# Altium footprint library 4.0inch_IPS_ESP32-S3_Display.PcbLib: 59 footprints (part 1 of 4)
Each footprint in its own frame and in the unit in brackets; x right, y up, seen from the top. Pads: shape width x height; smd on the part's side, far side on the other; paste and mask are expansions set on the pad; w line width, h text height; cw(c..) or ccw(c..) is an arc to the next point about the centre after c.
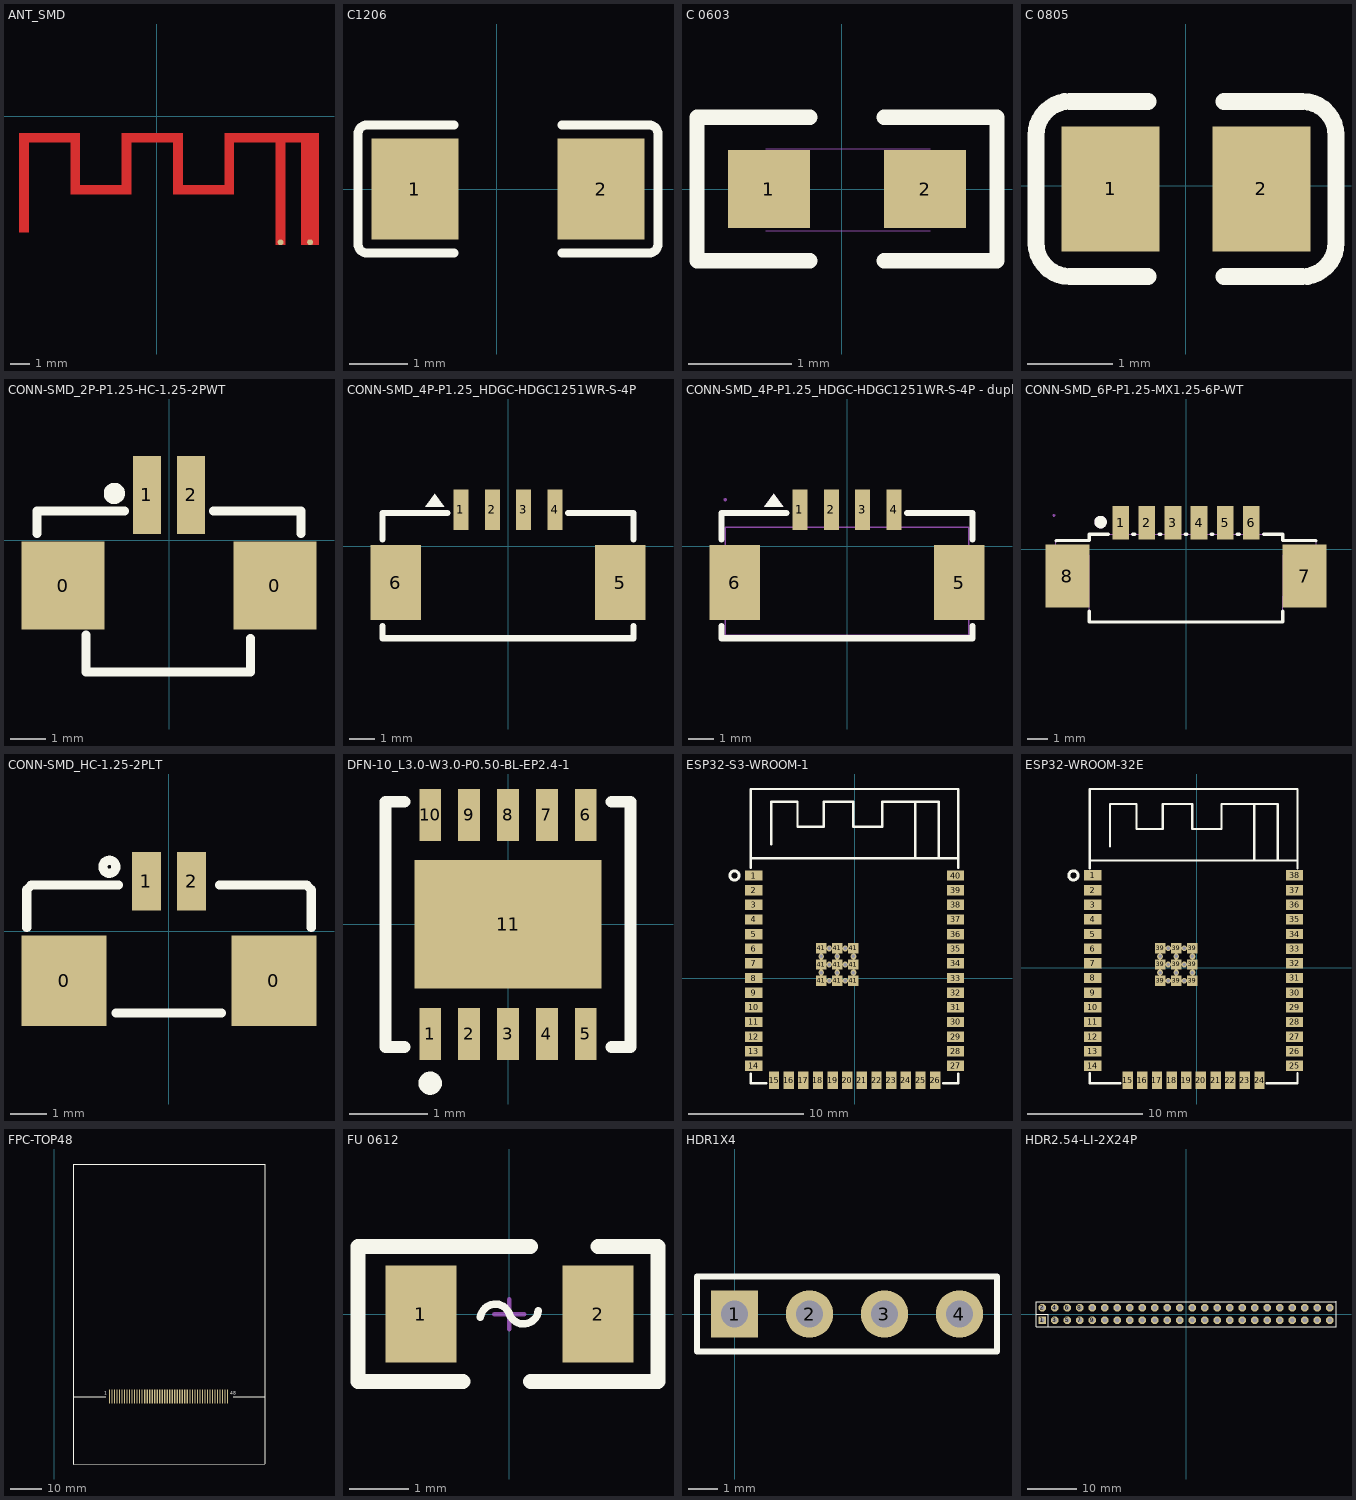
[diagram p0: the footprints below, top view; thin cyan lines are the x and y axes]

## ANT_SMD [mm]
pads (2):
  round 0.3 smd mask+0.102: 1(6.272,-6.391) 2(7.772,-6.391)
Top Layer:
  region: 8.222,-0.841 7.322,-0.841 7.322,-6.541 8.222,-6.541
  region: 6.522,-0.841 6.022,-0.841 6.022,-6.541 6.522,-6.541
  region: 8.222,-0.841 3.672,-0.841 3.672,-1.341 8.222,-1.341
  region: -6.478,-0.841 -6.978,-0.841 -6.978,-5.906 -6.478,-5.906
  region: -3.878,-0.841 -4.378,-0.841 -4.378,-3.981 -3.878,-3.981
  region: -1.278,-0.841 -1.778,-0.841 -1.778,-3.981 -1.278,-3.981
  region: 1.322,-0.841 0.822,-0.841 0.822,-3.981 1.322,-3.981
  region: 3.922,-0.841 3.422,-0.841 3.422,-3.981 3.922,-3.981
  region: 3.922,-3.481 0.856,-3.481 0.856,-3.981 3.922,-3.981
  region: -1.278,-3.481 -4.378,-3.481 -4.378,-3.981 -1.278,-3.981
  region: 1.322,-0.841 -1.778,-0.841 -1.778,-1.341 1.322,-1.341
  region: -3.878,-0.841 -6.978,-0.841 -6.978,-1.341 -3.878,-1.341

## C1206 [mm]
pads (2):
  rect 1.485x1.728 smd paste-100 mask+0.051: 1(-1.397,0) 2(1.788,0)
Top Overlay:
  lines w0.152: -0.731,-1.093 -2.216,-1.093 cw(c-2.216,-0.94) -2.368,-0.94 -2.368,0.94 cw(c-2.216,0.94) -2.216,1.093 -0.731,1.093 ; 1.122,-1.093 2.607,-1.093 ccw(c2.607,-0.94) 2.759,-0.94 2.759,0.94 ccw(c2.607,0.94) 2.607,1.093 1.122,1.093
Top Paste:
  region: 1.046,-0.764 1.046,-0.394 1.146,-0.294 1.45,-0.294 1.55,-0.194 1.55,0.194 1.45,0.294 1.146,0.294 1.046,0.394 1.046,0.764 1.146,0.864 2.431,0.864 2.531,0.764 2.531,-0.764 2.431,-0.864 1.146,-0.864
  region: -0.654,-0.764 -0.654,-0.394 -0.754,-0.294 -1.059,-0.294 -1.159,-0.194 -1.159,0.194 -1.059,0.294 -0.754,0.294 -0.654,0.394 -0.654,0.764 -0.754,0.864 -2.039,0.864 -2.139,0.764 -2.139,-0.764 -2.039,-0.864 -0.754,-0.864

## C 0603 [mm] "无极性贴片电容"
pads (2):
  rect 0.8x0.76 smd: 1(-0.711,0) 2(0.809,0)
Top Overlay:
  lines w0.15: -0.311,-0.7 -1.411,-0.7 -1.411,0.7 -0.311,0.7 ; 0.409,-0.7 1.509,-0.7 1.509,0.7 0.409,0.7
Mechanical 13:
  lines w0.01: -0.742,-0.406 0.858,-0.406 ; -0.742,0.394 0.858,0.394
3D body "C 0603.STEP": height 0.81, standoff -0.01, extent -0.742,-0.41 0.858,0.41

## C 0805 [mm] "无极性贴片电容"
height 0.5
pads (2):
  rect 1.16x1.47 smd: 1(-0.885,-0.039) 2(0.895,-0.039)
Top Overlay:
  lines w0.2: -0.445,-1.074 -1.365,-1.074 cw(c-1.365,-0.674) -1.765,-0.674 -1.765,0.596 cw(c-1.365,0.596) -1.365,0.996 -0.445,0.996 ; 0.455,-1.074 1.375,-1.074 ccw(c1.375,-0.674) 1.775,-0.674 1.775,0.596 ccw(c1.375,0.596) 1.375,0.996 0.455,0.996
3D body "User Library-0805 SMD Capacitor.STEP": height 0.77, standoff -0.01, extent -0.995,-0.664 1.005,0.586

## CONN-SMD_2P-P1.25-HC-1.25-2PWT [mm]
pads (4):
  rect 2.35x2.5 smd paste+0 mask+0.05: 0(-3.005,-1.285) 0(3.005,-1.285)
  rect 0.8x2.2 smd paste+0 mask+0.05: 1(-0.625,1.285) 2(0.625,1.285)
Top Overlay:
  circle w0.3: c-1.55,1.33 r0.15
  lines w0.254: -3.75,0.196 -3.75,0.835 -1.256,0.835 ; -2.36,-2.69 -2.36,-3.73 2.31,-3.73 2.31,-2.78 ; 1.256,0.835 3.75,0.835 3.75,0.196
3D body "User Library-ZH1_5-2P.STEP": height 5, standoff 0, extent -2.966,-2.968 3.034,2.232

## CONN-SMD_4P-P1.25_HDGC-HDGC1251WR-S-4P [mm]
pads (6):
  rect 0.6x1.6 smd mask+0.05: 1(-1.875,1.45) 2(-0.625,1.45) 3(0.625,1.45) 4(1.875,1.45)
  rect 2x3 smd mask+0.05: 5(4.475,-1.45) 6(-4.475,-1.45)
Top Overlay:
  region: -3.175,1.577 -3.302,1.577 -2.921,2.085 -2.54,1.577 -3.175,1.577
  lines w0.254: -5,-3.181 -5,-3.669 5,-3.669 5,-3.181 ; -5,0.281 -5,1.323 -2.413,1.323 ; 2.406,1.323 5,1.323 5,0.281
3D body "xb-x125-pcb-123.stp": height 3.5, standoff -0.1, extent -5.227,-3.975 5.163,1.525

## CONN-SMD_4P-P1.25_HDGC-HDGC1251WR-S-4P - duplicate [mm]
pads (6):
  rect 0.6x1.6 smd mask+0.05: 1(-1.875,1.45) 2(-0.625,1.45) 3(0.625,1.45) 4(1.875,1.45)
  rect 2x3 smd mask+0.05: 5(4.475,-1.45) 6(-4.475,-1.45)
Top Overlay:
  region: -3.175,1.577 -3.302,1.577 -2.921,2.085 -2.54,1.577 -3.175,1.577
  lines w0.254: -5,-3.181 -5,-3.669 5,-3.669 5,-3.181 ; -5,0.281 -5,1.323 -2.413,1.323 ; 2.406,1.323 5,1.323 5,0.281
Mechanical 6:
  region: -3.175,1.577 -3.302,1.577 -2.921,2.085 -2.54,1.577 -3.175,1.577
Mechanical 15:
  region: -4.85,-0.323 -3.65,-0.323 -3.65,-2.323 -4.85,-2.323
  region: 3.65,-0.323 4.85,-0.323 4.85,-2.323 3.65,-2.323
  region: -2.025,1.858 -1.725,1.858 -1.725,0.658 -2.025,0.658
  region: -0.775,1.858 -0.475,1.858 -0.475,0.658 -0.775,0.658
  region: 0.475,1.858 0.775,1.858 0.775,0.658 0.475,0.658
  region: 1.725,1.858 2.025,1.858 2.025,0.658 1.725,0.658
  region: -4.79,1.858 -4.79,1.883 -4.825,1.918 -4.875,1.918 -4.91,1.883 -4.91,1.858 -4.91,1.833 -4.875,1.798 -4.825,1.798 -4.79,1.833
  lines w0.051: -4.85,-3.542 4.85,-3.542 4.85,0.758 -4.85,0.758 -4.85,-3.542

## CONN-SMD_6P-P1.25-MX1.25-6P-WT [mm]
pads (8):
  rect 0.8x1.6 smd paste+0 mask+0.05: 1(-3.125,1.275) 2(-1.875,1.275) 3(-0.625,1.275) 4(0.625,1.275) 5(1.875,1.275) 6(3.125,1.275)
  rect 2.1x3 smd paste+0 mask+0.05: 7(5.675,-1.275) 8(-5.675,-1.275)
Top Overlay:
  circle w0.3: c-4.085,1.305 r0.15
  lines w0.152: -6.225,0.405 -6.225,0.425 -4.625,0.425 -4.625,0.725 -3.705,0.725 ; -4.625,-2.955 -4.625,-3.475 3.375,-3.475 4.625,-3.475 4.625,-2.955 ; -2.545,0.725 -2.455,0.725 ; -1.295,0.725 -1.205,0.725 ; -0.045,0.725 0.045,0.725 ; 2.455,0.725 2.545,0.725 ; 3.705,0.725 4.625,0.725 4.625,0.425 6.225,0.425 6.225,0.405 ; 1.205,0.725 1.295,0.725 1.205,0.725
Mechanical 6:
  circle w0.3: c-4.085,1.305 r0.15
Mechanical 15:
  region: -6.265,1.625 -6.266,1.649 -6.301,1.683 -6.349,1.683 -6.384,1.649 -6.385,1.625 -6.384,1.601 -6.349,1.567 -6.301,1.567 -6.266,1.601
  region: -6.125,-2.275 -6.325,-2.075 -6.325,-0.465 -6.125,-0.265 -4.625,-0.265 -4.625,-2.275
  region: 6.125,-0.265 6.325,-0.465 6.325,-2.075 6.125,-2.275 4.625,-2.275 4.625,-0.265
  region: 1.725,1.625 2.025,1.625 2.025,0.625 1.725,0.625
  region: 0.475,1.625 0.775,1.625 0.775,0.625 0.475,0.625
  region: -0.775,1.625 -0.475,1.625 -0.475,0.625 -0.775,0.625
  region: -2.025,1.625 -1.725,1.625 -1.725,0.625 -2.025,0.625
  region: -3.275,1.625 -2.975,1.625 -2.975,0.625 -3.275,0.625
  region: 2.975,1.625 3.275,1.625 3.275,0.625 2.975,0.625
  lines w0.051: -6.225,-2.275 -4.625,-2.275 -4.625,-3.475 4.625,-3.475 4.625,-2.275 6.225,-2.275 6.225,0.425 4.625,0.425 4.625,0.725 -4.625,0.725 -4.625,0.715 -4.625,0.425 -6.225,0.425 -6.225,-2.275

## CONN-SMD_HC-1.25-2PLT [mm]
pads (4):
  rect 2.35x2.5 smd paste+0 mask+0.05: 0(-2.9,-1.38) 0(2.9,-1.38)
  rect 0.8x1.62 smd paste+0 mask+0.05: 1(-0.625,1.38) 2(0.625,1.38)
Top Overlay:
  circle w0.254: c-1.651,1.778 r0.18
  lines w0.254: -3.937,0.101 -3.937,1.143 -3.81,1.27 -1.397,1.27 ; -1.47,-2.27 1.451,-2.27 ; 1.397,1.27 3.81,1.27 3.937,1.143 3.937,0.101
3D body "2pin.STEP": height 3.4, standoff 0, extent -3.759,-3.358 3.741,1.892

## DFN-10_L3.0-W3.0-P0.50-BL-EP2.4-1 [mm]
pads (11):
  rect 0.28x0.665 smd: 1(-1,-1.407) 2(-0.5,-1.407) 3(0,-1.407) 4(0.5,-1.407) 5(1,-1.407) 6(1,1.407) 7(0.5,1.407) 8(0,1.407) 9(-0.5,1.407) 10(-1,1.407)
  rect 2.4x1.65 smd: 11(0,0)
Top Overlay:
  circle w0.15: c-1,-2.04 r0.075
  lines w0.152: -1.331,-1.576 -1.576,-1.576 -1.576,1.576 -1.331,1.576 ; 1.331,-1.576 1.576,-1.576 1.576,1.576 1.331,1.576

## ESP32-S3-WROOM-1 [mm] "ESP32-S3-WROOM-1"
pads (49):
  rect 1.5x0.9 smd mask+0.05: 1(-8.75,8.895) 2(-8.75,7.625) 3(-8.75,6.355) 4(-8.75,5.085) 5(-8.75,3.815) 6(-8.75,2.545) 7(-8.75,1.275) 8(-8.75,0.005) 9(-8.75,-1.265) 10(-8.75,-2.535) 11(-8.75,-3.805) 12(-8.75,-5.075) 13(-8.75,-6.345) 14(-8.75,-7.615) 27(8.75,-7.615) 28(8.75,-6.345) 29(8.75,-5.075) 30(8.75,-3.805) 31(8.75,-2.535) 32(8.75,-1.265) 33(8.75,0.005) 34(8.75,1.275) 35(8.75,2.545) 36(8.75,3.815) 37(8.75,5.085) 38(8.75,6.355) 39(8.75,7.625) 40(8.75,8.895)
  rect 0.9x1.5 smd mask+0.05: 15(-6.985,-8.865) 16(-5.715,-8.865) 17(-4.445,-8.865) 18(-3.175,-8.865) 19(-1.905,-8.865) 20(-0.635,-8.865) 21(0.635,-8.865) 22(1.905,-8.865) 23(3.175,-8.865) 24(4.445,-8.865) 25(5.715,-8.865) 26(6.985,-8.865)
  rect 0.9x0.9 smd mask+0.051: 41(-2.9,-0.225) 41(-2.9,1.175) 41(-2.9,2.575) 41(-1.5,-0.225) 41(-1.5,1.175) 41(-1.5,2.575) 41(-0.1,-0.225) 41(-0.1,1.175) 41(-0.1,2.575)
via -0.8,-0.225 diameter 0.5 hole 0.3
via -2.2,-0.225 diameter 0.5 hole 0.3
via -2.2,1.175 diameter 0.5 hole 0.3
via -0.8,1.175 diameter 0.5 hole 0.3
via -0.8,2.575 diameter 0.5 hole 0.3
via -0.1,1.875 diameter 0.5 hole 0.3
via -0.1,0.475 diameter 0.5 hole 0.3
via -2.9,0.475 diameter 0.5 hole 0.3
via -2.9,1.875 diameter 0.5 hole 0.3
via -2.2,2.575 diameter 0.5 hole 0.3
via -1.5,0.475 diameter 0.5 hole 0.3
via -1.5,1.875 diameter 0.5 hole 0.3
Top Overlay:
  circle w0.254: c-10.414,8.895 r0.402
  lines w0.203: -9,-8.296 -9,-9.115 -7.666,-9.115 ; -9,9.576 -9,16.395 9,16.395 9,9.576 ; -9,10.395 9,10.395 ; -7.239,11.597 -7.239,15.28 -4.953,15.28 -4.953,13.121 -2.667,13.121 -2.667,15.28 -0.127,15.28 -0.127,13.121 2.413,13.121 2.413,15.28 5.265,15.28 5.265,10.395 ; 5.062,15.28 7.297,15.28 7.297,10.395 ; 7.666,-9.115 9,-9.115 9,-8.296
3D body "ESP32-S3-WROOM-1_20211021.STEP": height 3.1, standoff 0, extent -9,-9.115 9,16.385

## ESP32-WROOM-32E [mm]
pads (47):
  rect 1.5x0.9 smd mask+0.051: 1(-9.004,7.987) 2(-9.004,6.717) 3(-9.004,5.447) 4(-9.004,4.177) 5(-9.004,2.907) 6(-9.004,1.637) 7(-9.004,0.367) 8(-9.004,-0.903) 9(-9.004,-2.173) 10(-9.004,-3.443) 11(-9.004,-4.713) 12(-9.004,-5.983) 13(-9.004,-7.253) 14(-9.004,-8.523) 25(8.496,-8.523) 26(8.496,-7.253) 27(8.496,-5.983) 28(8.496,-4.713) 29(8.496,-3.443) 30(8.496,-2.173) 31(8.496,-0.903) 32(8.496,0.367) 33(8.496,1.637) 34(8.496,2.907) 35(8.496,4.177) 36(8.496,5.447) 37(8.496,6.717) 38(8.496,7.987)
  rect 0.9x1.5 smd mask+0.051: 15(-5.969,-9.774) 16(-4.699,-9.774) 17(-3.429,-9.774) 18(-2.159,-9.774) 19(-0.889,-9.774) 20(0.381,-9.774) 21(1.651,-9.774) 22(2.921,-9.774) 23(4.191,-9.774) 24(5.461,-9.774)
  rect 0.9x0.9 smd mask+0.051: 39(-3.154,-1.133) 39(-3.154,0.267) 39(-3.154,1.667) 39(-1.754,0.267) 39(-1.754,-1.133) 39(-1.754,1.667) 39(-0.354,-1.133) 39(-0.354,0.267) 39(-0.354,1.667)
via -1.754,0.967 diameter 0.5 hole 0.3
via -1.754,-0.433 diameter 0.5 hole 0.3
via -2.454,1.667 diameter 0.5 hole 0.3
via -3.154,0.967 diameter 0.5 hole 0.3
via -3.154,-0.433 diameter 0.5 hole 0.3
via -0.354,-0.433 diameter 0.5 hole 0.3
via -0.354,0.967 diameter 0.5 hole 0.3
via -1.054,1.667 diameter 0.5 hole 0.3
via -1.054,0.267 diameter 0.5 hole 0.3
via -2.454,0.267 diameter 0.5 hole 0.3
via -2.454,-1.133 diameter 0.5 hole 0.3
via -1.054,-1.133 diameter 0.5 hole 0.3
Top Overlay:
  circle w0.254: c-10.668,7.986 r0.402
  lines w0.203: -9.254,-9.15 -9.254,-10.023 -6.596,-10.023 ; -9.254,8.613 -9.254,15.476 8.746,15.477 8.746,8.614 ; -9.254,9.287 8.746,9.287 ; -7.493,10.489 -7.493,14.172 -5.207,14.172 -5.207,12.013 -2.921,12.013 -2.921,14.172 -0.381,14.172 -0.381,12.013 2.159,12.013 2.159,14.172 5.011,14.172 5.011,9.287 ; 4.808,14.172 7.043,14.172 7.043,9.287 ; 6.088,-10.023 8.746,-10.023 8.746,-9.15
3D body "ESP32-WROOM-32E_20210903.STEP": height 3.2, standoff 0.1, extent -9.254,-10.023 8.746,15.477

## FPC-TOP48 [mm]
pads (48):
  rect 0.4x4.5 smd: 1(17.542,-85.171) 2(18.342,-85.171) 3(19.142,-85.171) 4(19.942,-85.171) 5(20.742,-85.171) 6(21.542,-85.171) 7(22.342,-85.171) 8(23.142,-85.171) 9(23.942,-85.171) 10(24.742,-85.171) 11(25.542,-85.171) 12(26.342,-85.171) 13(27.142,-85.171) 14(27.942,-85.171) 15(28.742,-85.171) 16(29.542,-85.171) 17(30.342,-85.171) 18(31.142,-85.171) 19(31.942,-85.171) 20(32.742,-85.171) 21(33.542,-85.171) 22(34.342,-85.171) 23(35.142,-85.171) 24(35.942,-85.171) 25(36.742,-85.171) 26(37.542,-85.171) 27(38.342,-85.171) 28(39.142,-85.171) 29(39.942,-85.171) 30(40.742,-85.171) 31(41.542,-85.171) 32(42.342,-85.171) 33(43.142,-85.171) 34(43.942,-85.171) 35(44.742,-85.171) 36(45.542,-85.171) 37(46.342,-85.171) 38(47.142,-85.171) 39(47.942,-85.171) 40(48.742,-85.171) 41(49.542,-85.171) 42(50.342,-85.171) 43(51.142,-85.171) 44(51.942,-85.171) 45(52.742,-85.171) 46(53.542,-85.171) 47(54.342,-85.171) 48(55.142,-85.171)
Top Overlay:
  lines w0.2: 5.972,-85.171 16.312,-85.171 ; 56.882,-85.171 67.022,-85.171
  lines w0.254: 67.022,-11.171 5.972,-11.171 5.972,-106.601 67.022,-106.601 67.022,-11.144
  text "48" at 56.027,-84.492 h1.02
  text "1" at 15.968,-84.492 h1.02

## FU 0612 [mm] "贴片保险丝"
pads (2):
  rect 1.2x1.65 smd: 1(-1.5,0) 2(1.5,0)
Top Overlay:
  lines w0.127: -0.491,-0.058 cw(c-0.239,-0.087) 0,0 ccw(c0.239,0.087) 0.491,0.058
  lines w0.254: -0.786,-1.143 -2.564,-1.143 -2.564,1.143 -0.786,1.143 0.357,1.143 ; 0.357,-1.143 1.881,-1.143 ; 1.5,1.143 2.516,1.143 2.516,-1.143 1.627,-1.143
Mechanical 15:
  lines w0.076: -0.254,0 0.254,0 ; 0,-0.254 0,0.254
3D body "FU 0805.STEP": height 0.52, standoff 0, extent -1,-0.61 1,0.61

## HDR1X4 [mm] "Connector; Header; 4 Position"
pads (4):
  rect 1.6x1.6 hole 0.9: 1(0,0)
  round 1.6 hole 0.9: 2(2.54,0) 3(5.08,0) 4(7.62,0)
Top Overlay:
  lines w0.203: -1.27,-1.27 -1.27,1.27 8.89,1.27 8.89,-1.27 -1.27,-1.27

## HDR2.54-LI-2X24P [mm] "双排排针，24x2脚"
pads (48):
  rect 1.6x1.6 hole 0.9: 1(-29.21,-1.27)
  round 1.6 hole 0.9: 2(-29.21,1.27) 3(-26.67,-1.27) 4(-26.67,1.27) 5(-24.13,-1.27) 6(-24.13,1.27) 7(-21.59,-1.27) 8(-21.59,1.27) 9(-19.05,-1.27) 10(-19.05,1.27) 11(-16.51,-1.27) 12(-16.51,1.27) 13(-13.97,-1.27) 14(-13.97,1.27) 15(-11.43,-1.27) 16(-11.43,1.27) 17(-8.89,-1.27) 18(-8.89,1.27) 19(-6.35,-1.27) 20(-6.35,1.27) 21(-3.81,-1.27) 22(-3.81,1.27) 23(-1.27,-1.27) 24(-1.27,1.27) 25(1.27,-1.27) 26(1.27,1.27) 27(3.81,-1.27) 28(3.81,1.27) 29(6.35,-1.27) 30(6.35,1.27) 31(8.89,-1.27) 32(8.89,1.27) 33(11.43,-1.27) 34(11.43,1.27) 35(13.97,-1.27) 36(13.97,1.27) 37(16.51,-1.27) 38(16.51,1.27) 39(19.05,-1.27) 40(19.05,1.27) 41(21.59,-1.27) 42(21.59,1.27) 43(24.13,-1.27) 44(24.13,1.27) 45(26.67,-1.27) 46(26.67,1.27) 47(29.21,-1.27) 48(29.21,1.27)
Top Overlay:
  lines w0.2: -30.48,0 -27.94,0 -27.94,-2.54 ; 30.48,-2.54 -30.48,-2.54 -30.48,2.54 30.48,2.54
  lines w0.203: 30.48,-2.54 30.48,2.54
3D body "HDR2.54-1x2P.STEP": height 8.5, standoff -3, extent 20.32,-2.54 22.86,2.54
3D body "HDR2.54-1x2P.STEP": height 8.5, standoff -3, extent 25.4,-2.54 27.94,2.54
3D body "HDR2.54-1x2P.STEP": height 8.5, standoff -3, extent 22.86,-2.54 25.4,2.54
3D body "HDR2.54-1x2P.STEP": height 8.5, standoff -3, extent 12.7,-2.54 15.24,2.54
3D body "HDR2.54-1x2P.STEP": height 8.5, standoff -3, extent 15.24,-2.54 17.78,2.54
3D body "HDR2.54-1x2P.STEP": height 8.5, standoff -3, extent 7.62,-2.54 10.16,2.54
3D body "HDR2.54-1x2P.STEP": height 8.5, standoff -3, extent 10.16,-2.54 12.7,2.54
3D body "HDR2.54-1x2P.STEP": height 8.5, standoff -3, extent 17.78,-2.54 20.32,2.54
3D body "HDR2.54-1x2P.STEP": height 8.5, standoff -3, extent 0,-2.54 2.54,2.54
3D body "HDR2.54-1x2P.STEP": height 8.5, standoff -3, extent 2.54,-2.54 5.08,2.54
3D body "HDR2.54-1x2P.STEP": height 8.5, standoff -3, extent -5.08,-2.54 -2.54,2.54
3D body "HDR2.54-1x2P.STEP": height 8.5, standoff -3, extent -2.54,-2.54 0,2.54
3D body "HDR2.54-1x2P.STEP": height 8.5, standoff -3, extent 5.08,-2.54 7.62,2.54
3D body "HDR2.54-1x2P.STEP": height 8.5, standoff -3, extent -12.7,-2.54 -10.16,2.54
3D body "HDR2.54-1x2P.STEP": height 8.5, standoff -3, extent -10.16,-2.54 -7.62,2.54
3D body "HDR2.54-1x2P.STEP": height 8.5, standoff -3, extent -17.78,-2.54 -15.24,2.54
3D body "HDR2.54-1x2P.STEP": height 8.5, standoff -3, extent -15.24,-2.54 -12.7,2.54
3D body "HDR2.54-1x2P.STEP": height 8.5, standoff -3, extent -7.62,-2.54 -5.08,2.54
3D body "HDR2.54-1x2P.STEP": height 8.5, standoff -3, extent -25.4,-2.54 -22.86,2.54
3D body "HDR2.54-1x2P.STEP": height 8.5, standoff -3, extent -22.86,-2.54 -20.32,2.54
3D body "HDR2.54-1x2P.STEP": height 8.5, standoff -3, extent -30.48,-2.54 -27.94,2.54
3D body "HDR2.54-1x2P.STEP": height 8.5, standoff -3, extent -27.94,-2.54 -25.4,2.54
3D body "HDR2.54-1x2P.STEP": height 8.5, standoff -3, extent -20.32,-2.54 -17.78,2.54
3D body "HDR2.54-1x2P.STEP": height 8.5, standoff -3, extent 27.94,-2.54 30.48,2.54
